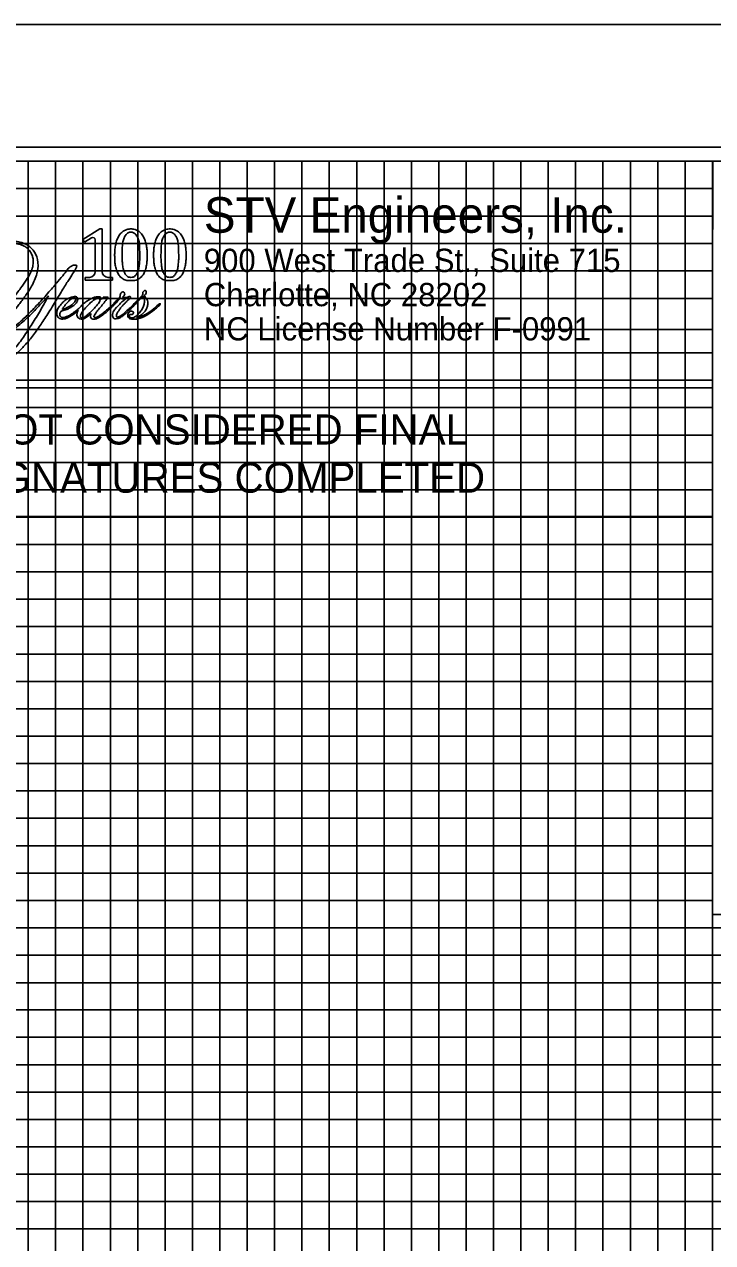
# Model space of a CAD drawing. Extents: x 3814791 to 3815465, y 1224203 to 1224643.
# Drawn here: x 3815327.8 to 3815378.1, y 1224554.2 to 1224643.2 of the extents above; entities that cross this region are included whole.
import ezdxf

# ---------------------------------------------------------------- set-up
doc = ezdxf.new("R2010")
doc.units = 0
for name, color, linetype in [('COGO Default Curve', 7, 'Continuous'), ('Exist Roads EOP', 7, 'Continuous'), ('Pattern 49', 7, 'Continuous'), ('Profile Utility Text', 7, 'Continuous'), ('Scratch_Level_1', 7, 'Continuous'), ('Sheet Data Field CELL', 7, 'Continuous'), ('Sheet Layout Plan Border', 7, 'Continuous')]:
    doc.layers.add(name, color=color, linetype=linetype)

msp = doc.modelspace()

# ---------------------------------------------------------------- linework, layer by layer
at = {"layer": 'COGO Default Curve'}
for p, q in [((3815298.107, 1224616.652), (3815378.107, 1224616.652)), ((3815378.107, 1224616.652), (3815378.107, 1224607.252)), ((3815378.107, 1224607.252), (3815298.107, 1224607.252))]:
    msp.add_line(p, q, dxfattribs=at)
at = {"layer": 'Exist Roads EOP'}
for p, q in [((3814878.107, 1224633.207), (3815378.107, 1224633.207)), ((3815378.107, 1224623.187), (3815378.132, 1224633.207)), ((3815438.107, 1224561.207), (3814878.107, 1224561.207)), ((3814878.107, 1224559.207), (3815438.107, 1224559.207))]:
    msp.add_line(p, q, dxfattribs=at)
for points in [[(3815458.107, 1224633.207), (3814858.107, 1224633.207), (3814858.107, 1224213.207), (3815458.107, 1224213.207)], [(3814878.107, 1224633.207), (3814878.107, 1224223.207), (3815438.107, 1224223.207), (3815438.107, 1224578.187), (3815378.107, 1224578.187), (3815378.107, 1224633.207)]]:
    msp.add_lwpolyline(points, close=True, dxfattribs=at)
for points in [[(3815328.107, 1224223.207), (3815328.107, 1224633.207), (3815348.107, 1224633.207), (3815348.107, 1224223.207)], [(3815330.107, 1224223.207), (3815330.107, 1224633.207), (3815332.107, 1224633.207), (3815332.107, 1224223.207)], [(3815334.107, 1224223.207), (3815334.107, 1224633.207), (3815336.107, 1224633.207), (3815336.107, 1224223.207)], [(3815338.107, 1224223.207), (3815338.107, 1224633.207), (3815358.107, 1224633.207), (3815358.107, 1224223.207)], [(3815340.107, 1224223.207), (3815340.107, 1224633.207), (3815342.107, 1224633.207), (3815342.107, 1224223.207)], [(3815344.107, 1224223.207), (3815344.107, 1224633.207), (3815346.107, 1224633.207), (3815346.107, 1224223.207)], [(3815350.107, 1224223.207), (3815350.107, 1224633.207), (3815352.107, 1224633.207), (3815352.107, 1224223.207)], [(3815354.107, 1224223.207), (3815354.107, 1224633.207), (3815356.107, 1224633.207), (3815356.107, 1224223.207)], [(3815360.107, 1224223.207), (3815360.107, 1224633.207), (3815362.107, 1224633.207), (3815362.107, 1224223.207)], [(3815364.107, 1224223.207), (3815364.107, 1224633.207), (3815366.107, 1224633.207), (3815366.107, 1224223.207)], [(3815368.107, 1224223.207), (3815368.107, 1224633.207)], [(3815370.107, 1224223.207), (3815370.107, 1224633.207), (3815372.107, 1224633.207), (3815372.107, 1224223.207)], [(3815374.107, 1224223.207), (3815374.107, 1224633.207), (3815376.107, 1224633.207), (3815376.107, 1224223.207)], [(3815378.107, 1224223.207), (3815378.107, 1224633.207), (3815388.627, 1224633.207)], [(3815418.137, 1224623.252), (3815418.137, 1224578.187), (3815378.107, 1224578.187), (3815378.107, 1224633.207), (3815418.137, 1224633.207), (3815418.137, 1224633.147)], [(3815378.087, 1224631.207), (3814878.107, 1224631.207), (3814878.107, 1224629.207), (3815378.087, 1224629.207)], [(3815378.087, 1224627.207), (3814878.107, 1224627.207), (3814878.107, 1224625.207), (3815378.087, 1224625.207)], [(3815378.087, 1224603.207), (3814858.147, 1224603.207), (3814858.147, 1224623.187), (3815378.087, 1224623.187)], [(3815378.087, 1224620.907), (3814878.107, 1224620.907), (3814878.107, 1224619.207), (3815378.087, 1224619.207)], [(3815378.087, 1224617.207), (3814878.107, 1224617.207), (3814878.107, 1224615.207), (3815378.087, 1224615.207)], [(3814858.107, 1224613.207), (3815378.087, 1224613.207)], [(3815378.087, 1224611.207), (3814878.107, 1224611.207), (3814878.107, 1224609.207), (3815378.087, 1224609.207)], [(3815378.107, 1224607.207), (3814878.107, 1224607.207), (3814878.107, 1224605.207), (3815378.087, 1224605.207)], [(3815378.087, 1224601.207), (3814878.107, 1224601.207), (3814878.107, 1224599.207), (3815378.087, 1224599.207)], [(3815378.087, 1224597.207), (3814878.107, 1224597.207), (3814878.107, 1224595.207), (3815378.087, 1224595.207)], [(3815378.087, 1224593.207), (3814858.107, 1224593.207), (3814858.107, 1224573.187), (3815458.107, 1224573.187)], [(3815378.087, 1224591.207), (3814878.107, 1224591.207), (3814878.107, 1224589.207), (3815378.087, 1224589.207)], [(3815378.087, 1224587.207), (3814878.107, 1224587.207), (3814878.107, 1224585.207), (3815378.087, 1224585.207)], [(3815458.107, 1224563.207), (3814858.107, 1224563.207), (3814858.107, 1224583.207), (3815378.087, 1224583.207)], [(3815378.087, 1224581.207), (3814878.107, 1224581.207), (3814878.107, 1224579.207), (3815378.087, 1224579.207)], [(3815438.107, 1224577.207), (3814878.107, 1224577.207), (3814878.107, 1224577.207), (3814878.107, 1224569.207), (3815438.107, 1224569.207)], [(3815438.107, 1224577.207), (3814878.107, 1224577.207), (3814878.107, 1224577.207), (3814878.107, 1224569.207), (3815458.107, 1224569.207)], [(3814878.107, 1224575.207), (3815438.107, 1224575.207)], [(3815438.107, 1224571.207), (3814878.107, 1224571.207)], [(3815438.107, 1224567.207), (3814878.107, 1224567.207), (3814878.107, 1224565.207), (3815438.107, 1224565.207)], [(3815438.107, 1224557.207), (3814878.107, 1224557.207), (3814878.107, 1224555.207), (3815438.107, 1224555.207)]]:
    msp.add_lwpolyline(points, dxfattribs=at)
at = {"layer": 'Pattern 49'}
msp.add_lwpolyline([(3815463.107, 1224634.227), (3814796.507, 1224634.227), (3814796.507, 1224212.187), (3815463.107, 1224212.187)], close=True, dxfattribs=at)
at = {"layer": 'Profile Utility Text'}
for points in [[(3815298.107, 1224633.207), (3815378.107, 1224633.207), (3815378.107, 1224607.252), (3815333.021, 1224607.252), (3815318.649, 1224607.252), (3815298.107, 1224607.252)], [(3815378.107, 1224578.187), (3815458.107, 1224578.187), (3815458.107, 1224569.207), (3815416.023, 1224569.207), (3815402.086, 1224569.207), (3815378.107, 1224569.207)]]:
    msp.add_lwpolyline(points, close=True, dxfattribs=at)
at = {"layer": 'Scratch_Level_1'}
msp.add_lwpolyline([(3815464.907, 1224643.207), (3814791.307, 1224643.207), (3814791.307, 1224203.207), (3815464.907, 1224203.207)], close=True, dxfattribs=at)
at = {"layer": 'Sheet Data Field CELL'}
msp.add_lwpolyline([(3815378.107, 1224578.187), (3815458.107, 1224578.187), (3815458.107, 1224569.207), (3815378.107, 1224569.207)], close=True, dxfattribs=at)
at = {"layer": 'Sheet Layout Plan Border'}
for p, q in [((3815333.337, 1224628.261), (3815332.095, 1224627.499)), ((3815332.222, 1224627.301), (3815332.737, 1224627.617)), ((3815333.51, 1224628.261), (3815333.337, 1224628.261)), ((3815333.51, 1224625.153), (3815333.51, 1224628.261)), ((3815332.095, 1224627.499), (3815332.222, 1224627.301)), ((3815333.008, 1224627.465), (3815333.008, 1224625.153)), ((3815332.581, 1224624.726), (3815332.261, 1224624.726)), ((3815332.261, 1224624.726), (3815332.261, 1224624.517)), ((3815332.261, 1224624.517), (3815334.258, 1224624.517)), ((3815334.258, 1224624.726), (3815333.938, 1224624.726)), ((3815334.258, 1224624.517), (3815334.258, 1224624.726)), ((3815335.613, 1224624.718), (3815335.61, 1224624.718)), ((3815335.611, 1224624.489), (3815335.612, 1224624.489)), ((3815338.456, 1224624.718), (3815338.454, 1224624.718)), ((3815338.455, 1224624.489), (3815338.455, 1224624.489))]:
    msp.add_line(p, q, dxfattribs=at)
msp.add_lwpolyline([(3815298.107, 1224633.207), (3815378.107, 1224633.207), (3815378.107, 1224616.652), (3815298.107, 1224616.652)], close=True, dxfattribs=at)
for centre, radius, start, end in [((3815332.83, 1224627.465), 0.178, 360, 121.52681), ((3815332.581, 1224625.153), 0.428, 270, 0), ((3815333.938, 1224625.153), 0.428, 180, 270)]:
    msp.add_arc(centre, radius, start, end, dxfattribs=at)
for points, degree in [([(3815335.611, 1224628.261), (3815335.58, 1224628.26), (3815335.478, 1224628.257), (3815335.31, 1224628.228), (3815335.097, 1224628.14), (3815334.88, 1224627.971), (3815334.681, 1224627.703), (3815334.561, 1224627.388), (3815334.47, 1224627.04), (3815334.43, 1224626.713), (3815334.423, 1224626.482), (3815334.421, 1224626.389)], 3), ([(3815334.964, 1224626.389), (3815334.968, 1224626.538), (3815334.977, 1224626.832), (3815334.991, 1224627.239), (3815335.078, 1224627.566), (3815335.193, 1224627.785), (3815335.31, 1224627.917), (3815335.425, 1224627.992), (3815335.513, 1224628.02), (3815335.575, 1224628.024), (3815335.611, 1224628.027)], 3), ([(3815336.802, 1224626.389), (3815336.799, 1224626.482), (3815336.793, 1224626.713), (3815336.753, 1224627.04), (3815336.662, 1224627.388), (3815336.541, 1224627.703), (3815336.342, 1224627.971), (3815336.126, 1224628.14), (3815335.913, 1224628.228), (3815335.745, 1224628.257), (3815335.643, 1224628.26), (3815335.611, 1224628.261)], 3), ([(3815335.611, 1224628.027), (3815335.648, 1224628.024), (3815335.71, 1224628.02), (3815335.798, 1224627.992), (3815335.913, 1224627.917), (3815336.03, 1224627.785), (3815336.145, 1224627.566), (3815336.232, 1224627.239), (3815336.246, 1224626.832), (3815336.254, 1224626.538), (3815336.259, 1224626.389)], 3), ([(3815338.455, 1224628.261), (3815338.424, 1224628.26), (3815338.321, 1224628.257), (3815338.154, 1224628.228), (3815337.94, 1224628.14), (3815337.724, 1224627.971), (3815337.525, 1224627.703), (3815337.405, 1224627.388), (3815337.314, 1224627.04), (3815337.274, 1224626.713), (3815337.267, 1224626.482), (3815337.265, 1224626.389)], 3), ([(3815337.808, 1224626.389), (3815337.812, 1224626.538), (3815337.821, 1224626.832), (3815337.835, 1224627.239), (3815337.922, 1224627.566), (3815338.036, 1224627.785), (3815338.153, 1224627.917), (3815338.269, 1224627.992), (3815338.357, 1224628.02), (3815338.419, 1224628.024), (3815338.455, 1224628.027)], 3), ([(3815339.646, 1224626.389), (3815339.643, 1224626.482), (3815339.636, 1224626.713), (3815339.597, 1224627.04), (3815339.505, 1224627.388), (3815339.385, 1224627.703), (3815339.186, 1224627.971), (3815338.97, 1224628.14), (3815338.756, 1224628.228), (3815338.589, 1224628.257), (3815338.486, 1224628.26), (3815338.455, 1224628.261)], 3), ([(3815338.455, 1224628.027), (3815338.491, 1224628.024), (3815338.553, 1224628.02), (3815338.641, 1224627.992), (3815338.757, 1224627.917), (3815338.874, 1224627.785), (3815338.989, 1224627.566), (3815339.075, 1224627.239), (3815339.09, 1224626.832), (3815339.098, 1224626.538), (3815339.102, 1224626.389)], 3), ([(3815329.579, 1224623.37), (3815329.48, 1224623.182), (3815329.145, 1224622.541), (3815328.559, 1224621.583), (3815327.905, 1224620.564), (3815327.301, 1224619.72), (3815326.755, 1224619.129), (3815326.278, 1224618.692), (3815325.912, 1224618.471), (3815325.578, 1224618.312), (3815325.273, 1224618.284), (3815325.005, 1224618.326), (3815324.819, 1224618.475), (3815324.729, 1224618.652), (3815324.739, 1224618.8), (3815324.823, 1224618.892), (3815324.952, 1224618.897), (3815325.113, 1224618.904), (3815325.316, 1224618.974), (3815325.376, 1224619.217), (3815325.208, 1224619.41), (3815324.944, 1224619.393), (3815324.741, 1224619.217), (3815324.57, 1224618.983), (3815324.588, 1224618.694), (3815324.672, 1224618.439), (3815324.863, 1224618.251), (3815325.148, 1224618.157), (3815325.447, 1224618.169), (3815325.782, 1224618.232), (3815326.176, 1224618.393), (3815326.609, 1224618.663), (3815327.118, 1224619.03), (3815327.702, 1224619.583), (3815328.276, 1224620.224), (3815328.842, 1224620.996), (3815329.371, 1224621.797), (3815330.015, 1224622.822), (3815330.587, 1224623.772), (3815331.072, 1224624.563), (3815331.375, 1224625.002), (3815331.546, 1224625.309), (3815331.648, 1224625.457), (3815331.669, 1224625.635), (3815331.494, 1224625.613), (3815331.348, 1224625.603), (3815331.179, 1224625.505), (3815330.995, 1224625.331), (3815330.752, 1224624.985), (3815330.309, 1224624.456), (3815329.642, 1224623.687), (3815328.836, 1224622.757), (3815327.977, 1224621.898), (3815327.33, 1224621.296), (3815326.897, 1224621.026), (3815326.704, 1224620.914), (3815326.492, 1224620.904), (3815326.428, 1224621.1), (3815326.477, 1224621.314), (3815326.661, 1224621.749), (3815326.984, 1224622.165), (3815327.421, 1224622.729), (3815327.888, 1224623.348), (3815328.443, 1224624.171), (3815328.82, 1224625.107), (3815328.854, 1224626.058), (3815328.487, 1224626.765), (3815327.968, 1224627.164), (3815327.513, 1224627.304), (3815327.23, 1224627.348), (3815327.124, 1224627.359)], 3), ([(3815327.277, 1224627.183), (3815327.281, 1224627.182), (3815327.347, 1224627.169), (3815327.47, 1224627.146), (3815327.702, 1224627.074), (3815327.938, 1224626.939), (3815328.175, 1224626.739), (3815328.324, 1224626.502), (3815328.443, 1224626.242), (3815328.481, 1224625.926), (3815328.461, 1224625.507), (3815328.279, 1224625.035), (3815327.959, 1224624.515), (3815327.58, 1224623.964), (3815327.008, 1224623.21), (3815326.426, 1224622.443), (3815326.116, 1224621.654), (3815326.097, 1224621.181), (3815326.2, 1224620.905), (3815326.385, 1224620.765), (3815326.559, 1224620.758), (3815326.796, 1224620.797), (3815327.062, 1224620.953), (3815327.382, 1224621.175), (3815327.809, 1224621.568), (3815328.345, 1224622.056), (3815328.964, 1224622.718), (3815329.362, 1224623.14), (3815329.579, 1224623.37)], 3), ([(3815334.421, 1224626.389), (3815334.423, 1224626.313), (3815334.43, 1224626.114), (3815334.434, 1224625.794), (3815334.504, 1224625.445), (3815334.6, 1224625.113), (3815334.756, 1224624.846), (3815334.947, 1224624.65), (3815335.225, 1224624.499), (3815335.458, 1224624.493), (3815335.611, 1224624.489)], 3), ([(3815335.61, 1224624.718), (3815335.559, 1224624.722), (3815335.437, 1224624.732), (3815335.272, 1224624.854), (3815335.128, 1224625.072), (3815335.027, 1224625.369), (3815334.993, 1224625.723), (3815334.958, 1224626.064), (3815334.962, 1224626.287), (3815334.964, 1224626.389)], 3), ([(3815335.612, 1224624.489), (3815335.765, 1224624.493), (3815335.998, 1224624.499), (3815336.276, 1224624.65), (3815336.467, 1224624.846), (3815336.622, 1224625.113), (3815336.718, 1224625.445), (3815336.789, 1224625.794), (3815336.793, 1224626.114), (3815336.799, 1224626.313), (3815336.802, 1224626.389)], 3), ([(3815336.259, 1224626.389), (3815336.261, 1224626.287), (3815336.265, 1224626.064), (3815336.23, 1224625.723), (3815336.196, 1224625.369), (3815336.094, 1224625.072), (3815335.951, 1224624.854), (3815335.786, 1224624.732), (3815335.664, 1224624.722), (3815335.613, 1224624.718)], 3), ([(3815337.265, 1224626.389), (3815337.267, 1224626.313), (3815337.274, 1224626.114), (3815337.277, 1224625.794), (3815337.348, 1224625.445), (3815337.444, 1224625.113), (3815337.6, 1224624.846), (3815337.791, 1224624.65), (3815338.069, 1224624.499), (3815338.301, 1224624.493), (3815338.455, 1224624.489)], 3), ([(3815338.454, 1224624.718), (3815338.403, 1224624.722), (3815338.281, 1224624.732), (3815338.115, 1224624.854), (3815337.972, 1224625.072), (3815337.87, 1224625.369), (3815337.837, 1224625.723), (3815337.802, 1224626.064), (3815337.806, 1224626.287), (3815337.808, 1224626.389)], 3), ([(3815338.455, 1224624.489), (3815338.609, 1224624.493), (3815338.842, 1224624.499), (3815339.119, 1224624.65), (3815339.31, 1224624.846), (3815339.466, 1224625.113), (3815339.562, 1224625.445), (3815339.633, 1224625.794), (3815339.636, 1224626.114), (3815339.643, 1224626.313), (3815339.646, 1224626.389)], 3), ([(3815339.102, 1224626.389), (3815339.104, 1224626.287), (3815339.108, 1224626.064), (3815339.074, 1224625.723), (3815339.04, 1224625.369), (3815338.938, 1224625.072), (3815338.795, 1224624.854), (3815338.629, 1224624.732), (3815338.508, 1224624.722), (3815338.456, 1224624.718)], 3), ([(3815333.471, 1224623.121), (3815333.462, 1224623.211), (3815333.416, 1224623.286), (3815333.222, 1224623.302), (3815332.959, 1224623.285), (3815332.68, 1224623.157), (3815332.445, 1224623.018), (3815332.199, 1224622.849), (3815331.979, 1224622.631), (3815331.756, 1224622.4), (3815331.433, 1224622.156), (3815331.315, 1224622.078), (3815331.115, 1224621.94), (3815330.901, 1224621.853), (3815330.721, 1224621.773), (3815330.575, 1224621.785), (3815330.472, 1224621.839), (3815330.405, 1224621.944), (3815330.406, 1224622.082), (3815330.469, 1224622.178), (3815330.511, 1224622.273), (3815330.641, 1224622.29), (3815330.819, 1224622.35), (3815331.038, 1224622.423), (3815331.266, 1224622.564), (3815331.503, 1224622.714), (3815331.684, 1224622.926), (3815331.765, 1224623.171), (3815331.633, 1224623.326), (3815331.478, 1224623.322), (3815331.273, 1224623.305), (3815331.014, 1224623.178), (3815330.707, 1224622.985), (3815330.449, 1224622.69), (3815330.232, 1224622.425), (3815330.179, 1224622.159), (3815330.193, 1224621.979), (3815330.269, 1224621.815), (3815330.4, 1224621.722), (3815330.552, 1224621.666), (3815330.735, 1224621.672), (3815330.989, 1224621.761), (3815331.254, 1224621.924), (3815331.535, 1224622.108), (3815331.685, 1224622.249), (3815331.757, 1224622.317)], 3), ([(3815330.585, 1224622.374), (3815330.635, 1224622.45), (3815330.728, 1224622.589), (3815330.903, 1224622.828), (3815331.081, 1224623.025), (3815331.277, 1224623.157), (3815331.387, 1224623.234), (3815331.488, 1224623.253), (3815331.561, 1224623.229), (3815331.607, 1224623.146), (3815331.553, 1224623.011), (3815331.452, 1224622.87), (3815331.293, 1224622.715), (3815331.099, 1224622.577), (3815330.905, 1224622.498), (3815330.734, 1224622.423), (3815330.642, 1224622.393), (3815330.585, 1224622.374)], 3), ([(3815332.66, 1224622.188), (3815332.586, 1224622.125), (3815332.415, 1224621.98), (3815332.216, 1224621.801), (3815332.024, 1224621.747), (3815331.916, 1224621.799), (3815331.92, 1224621.947), (3815332.013, 1224622.158), (3815332.279, 1224622.491), (3815332.578, 1224622.804), (3815332.849, 1224623.04), (3815333.009, 1224623.139), (3815333.144, 1224623.182), (3815333.269, 1224623.196), (3815333.406, 1224623.068), (3815333.238, 1224622.821), (3815333.052, 1224622.594), (3815332.842, 1224622.367), (3815332.708, 1224622.235), (3815332.66, 1224622.188)], 3), ([(3815332.691, 1224622.087), (3815332.681, 1224622.051), (3815332.657, 1224621.964), (3815332.645, 1224621.822), (3815332.737, 1224621.675), (3815332.915, 1224621.667), (3815333.167, 1224621.7), (3815333.461, 1224621.922), (3815333.803, 1224622.16), (3815334.074, 1224622.427), (3815334.324, 1224622.658), (3815334.571, 1224622.916), (3815334.749, 1224623.108), (3815334.848, 1224623.215)], 3), ([(3815336.019, 1224621.775), (3815336.06, 1224621.797), (3815336.194, 1224621.867), (3815336.403, 1224622.012), (3815336.61, 1224622.199), (3815336.765, 1224622.425), (3815336.845, 1224622.676), (3815336.854, 1224622.946), (3815336.771, 1224623.146), (3815336.671, 1224623.263), (3815336.635, 1224623.342), (3815336.592, 1224623.387), (3815336.608, 1224623.448), (3815336.675, 1224623.472), (3815336.718, 1224623.556), (3815336.742, 1224623.646), (3815336.707, 1224623.76), (3815336.587, 1224623.77), (3815336.516, 1224623.686), (3815336.464, 1224623.581), (3815336.491, 1224623.428), (3815336.326, 1224623.304), (3815336.156, 1224623.103), (3815335.85, 1224622.807), (3815335.545, 1224622.496), (3815335.265, 1224622.259), (3815335.104, 1224622.103), (3815334.969, 1224621.986), (3815334.827, 1224621.894), (3815334.717, 1224621.823), (3815334.576, 1224621.801), (3815334.538, 1224621.936), (3815334.57, 1224622.041), (3815334.653, 1224622.193), (3815334.776, 1224622.379), (3815334.944, 1224622.599), (3815335.114, 1224622.78), (3815335.287, 1224622.949), (3815335.431, 1224623.106), (3815335.557, 1224623.191), (3815335.612, 1224623.271), (3815335.543, 1224623.356), (3815335.429, 1224623.3), (3815335.306, 1224623.256), (3815335.194, 1224623.267), (3815334.981, 1224623.267), (3815335.043, 1224623.326), (3815335.081, 1224623.367), (3815335.168, 1224623.438), (3815335.167, 1224623.582), (3815335.069, 1224623.677), (3815334.948, 1224623.654), (3815334.869, 1224623.563), (3815334.822, 1224623.454), (3815334.84, 1224623.365), (3815334.79, 1224623.235), (3815334.627, 1224623.094), (3815334.384, 1224622.842), (3815334.095, 1224622.556), (3815333.733, 1224622.245), (3815333.432, 1224622), (3815333.187, 1224621.848), (3815333.062, 1224621.782), (3815332.967, 1224621.774), (3815332.91, 1224621.814), (3815332.906, 1224621.884), (3815332.941, 1224621.953), (3815333.026, 1224622.096), (3815333.175, 1224622.304), (3815333.454, 1224622.631), (3815333.715, 1224622.953), (3815333.894, 1224623.192), (3815333.949, 1224623.266)], 3), ([(3815333.594, 1224623.266), (3815333.553, 1224623.217), (3815333.512, 1224623.169), (3815333.471, 1224623.121)], 2), ([(3815333.949, 1224623.266), (3815333.831, 1224623.266), (3815333.712, 1224623.266), (3815333.594, 1224623.266)], 2), ([(3815335.217, 1224623.141), (3815335.128, 1224623.075), (3815334.947, 1224622.94), (3815334.738, 1224622.72), (3815334.549, 1224622.526), (3815334.41, 1224622.365), (3815334.314, 1224622.196), (3815334.258, 1224622.024), (3815334.258, 1224621.823), (3815334.43, 1224621.678), (3815334.638, 1224621.699), (3815334.843, 1224621.78), (3815335.074, 1224621.963), (3815335.378, 1224622.208), (3815335.855, 1224622.693), (3815336.23, 1224623.074), (3815336.49, 1224623.339)], 3), ([(3815334.848, 1224623.215), (3815334.883, 1224623.195), (3815334.96, 1224623.15), (3815335.091, 1224623.139), (3815335.179, 1224623.14), (3815335.217, 1224623.141)], 3), ([(3815336.49, 1224623.339), (3815336.515, 1224623.313), (3815336.589, 1224623.236), (3815336.602, 1224623.025), (3815336.595, 1224622.777), (3815336.466, 1224622.486), (3815336.298, 1224622.192), (3815336.08, 1224621.959), (3815335.894, 1224621.821), (3815335.741, 1224621.76), (3815335.605, 1224621.765), (3815335.519, 1224621.825), (3815335.476, 1224621.9), (3815335.505, 1224621.977), (3815335.561, 1224622.028), (3815335.635, 1224622.021), (3815335.719, 1224622.007), (3815335.793, 1224622.075), (3815335.826, 1224622.172), (3815335.723, 1224622.253), (3815335.579, 1224622.262), (3815335.451, 1224622.156), (3815335.384, 1224622.019), (3815335.374, 1224621.852), (3815335.498, 1224621.708), (3815335.74, 1224621.666), (3815336.033, 1224621.658), (3815336.353, 1224621.762), (3815336.686, 1224621.906), (3815337.005, 1224622.121), (3815337.357, 1224622.367), (3815337.59, 1224622.59), (3815337.754, 1224622.721), (3815337.766, 1224622.817), (3815337.689, 1224622.807), (3815337.602, 1224622.72), (3815337.461, 1224622.582), (3815337.211, 1224622.385), (3815336.951, 1224622.182), (3815336.663, 1224622.006), (3815336.412, 1224621.881), (3815336.201, 1224621.776), (3815336.067, 1224621.775), (3815336.019, 1224621.775)], 3), ([(3815331.757, 1224622.317), (3815331.731, 1224622.268), (3815331.687, 1224622.181), (3815331.656, 1224622.025), (3815331.678, 1224621.855), (3815331.8, 1224621.719), (3815331.968, 1224621.659), (3815332.141, 1224621.672), (3815332.308, 1224621.762), (3815332.446, 1224621.868), (3815332.574, 1224621.983), (3815332.651, 1224622.052), (3815332.691, 1224622.087)], 3)]:
    msp.add_open_spline(points, degree=degree, dxfattribs=at)

# ---------------------------------------------------------------- texts
at = {"layer": 'COGO Default Curve'}
for s, p in [('DOCUMENT NOT CONSIDERED FINAL', (3815306.627, 1224612.514)), ('UNLESS ALL SIGNATURES COMPLETED', (3815304.599, 1224608.994))]:
    msp.add_text(s, height=2.2, rotation=360, dxfattribs=at).set_placement(p)
at = {"layer": 'Sheet Layout Plan Border'}
for s, height, p in [('STV Engineers, Inc.', 2.6, (3815340.936, 1224627.982)), ('900 West Trade St., Suite 715', 1.7, (3815340.936, 1224625.116)), ('Charlotte, NC 28202', 1.7, (3815340.936, 1224622.616)), ('NC License Number F-0991', 1.7, (3815340.936, 1224620.116))]:
    msp.add_text(s, height=height, rotation=360, dxfattribs=at).set_placement(p)

doc.saveas('drawing.dxf')
